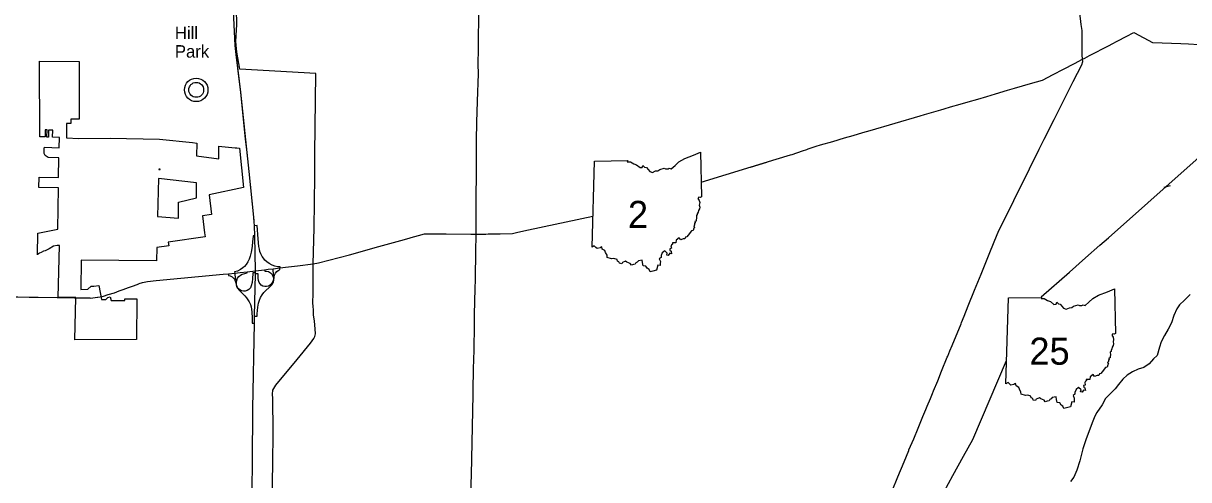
# Model space of a CAD drawing. Extents: x 0 to 750, y 0 to 507.
# Drawn here: x 229.9 to 327.4, y 215 to 253.1 of the extents above; entities that cross this region are included whole.
import ezdxf

# ---------------------------------------------------------------- set-up
doc = ezdxf.new("R2010")
doc.units = 0
for name, color, linetype in [('DV_X_Corp_Line', 7, 'Continuous'), ('GM_P_US_Alignment', 7, 'Continuous'), ('GM_X_Corporation_Text', 7, 'Continuous'), ('GM_X_County', 7, 'Continuous'), ('GM_X_Interchange_Ramps', 7, 'Continuous'), ('GM_X_Interstate_Route', 7, 'Continuous'), ('GM_X_Rail_Line', 7, 'Continuous'), ('GM_X_State_Route', 7, 'Continuous'), ('GM_X_US_Route', 7, 'Continuous')]:
    doc.layers.add(name, color=color, linetype=linetype)

msp = doc.modelspace()

# ---------------------------------------------------------------- linework, layer by layer
at = {"layer": 'DV_X_Corp_Line'}
for points in [[(250.728, 213.571), (250.775, 216.198), (250.812, 218.983), (250.784, 221.74), (250.771, 222.115), (250.783, 222.441), (251.043, 222.865), (252.824, 224.992), (253.938, 226.351), (254.223, 226.765), (254.302, 226.926), (254.355, 227.142), (254.341, 227.553), (254.265, 228.214), (254.201, 228.725), (254.182, 229.151), (254.149, 229.431), (254.127, 229.722), (254.15, 230.504), (254.168, 231.793), (254.166, 232.98), (254.25, 235.984), (254.29, 240.326), (254.295, 242.177), (254.377, 248.889), (248.037, 249.252), (247.783, 250.688), (247.693, 251.561), (247.74, 252.545), (247.768, 252.975), (247.752, 254.307)], [(327.486, 230.432), (327.021, 229.948), (326.609, 229.574), (326.377, 229.222), (326.142, 228.674), (325.925, 228.071), (325.66, 227.538), (325.354, 226.992), (325.079, 226.465), (324.941, 226.02), (324.733, 225.326), (324.447, 225.05), (324.084, 224.636), (323.628, 224.337), (323.164, 224.18), (322.675, 223.963), (322.229, 223.695), (321.877, 223.36), (321.513, 222.9), (321.216, 222.544), (320.752, 222.065), (320.42, 221.73), (320.13, 221.218), (319.943, 220.942), (319.698, 220.579), (319.537, 220.25), (319.301, 219.703), (319.101, 219.184), (318.796, 218.361), (318.52, 217.538), (318.261, 216.544), (318.011, 215.76), (317.77, 215.163), (317.497, 214.791)]]:
    msp.add_lwpolyline(points, dxfattribs=at)
for points in [[(231.101, 233.751), (231.128, 235.547), (232.799, 235.875), (232.858, 239.353), (231.22, 239.38), (231.234, 240.233), (232.873, 240.208), (232.901, 241.86), (231.986, 241.887), (231.757, 242.054), (231.679, 242.205), (231.675, 242.326), (231.675, 242.509), (231.679, 242.592), (231.703, 242.73), (232.924, 242.693), (232.947, 243.557), (232.376, 243.574), (232.382, 244.171), (232.033, 244.174), (232.025, 243.584), (231.9, 243.588), (231.908, 244.175), (231.752, 244.177), (231.743, 243.592), (231.31, 243.604), (231.266, 249.931), (234.598, 249.898), (234.592, 245.075), (233.902, 245.076), (233.901, 244.716), (233.537, 244.716), (233.535, 243.527), (234.578, 243.474), (237.198, 243.497), (241.303, 243.418), (244.056, 243.124), (244.419, 243.076), (244.416, 242.005), (246.261, 241.758), (246.267, 242.832), (246.53, 242.802), (247.641, 242.693), (247.781, 242.676), (247.997, 242.645), (248.343, 239.366), (245.454, 238.751), (245.654, 237.122), (244.899, 237.015), (245.076, 235.574), (245.117, 235.239), (242.047, 234.807), (242.087, 234.485), (241.085, 234.344), (241.06, 233.249), (234.764, 233.302), (234.735, 230.859), (235.319, 230.869), (235.587, 231.138), (235.653, 231.134), (235.748, 231.132), (235.812, 231.138), (236.226, 231.17), (236.457, 230.014), (236.83, 230.021), (236.994, 230.185), (237.188, 230.231), (237.277, 229.942), (238.402, 229.922), (238.402, 230.072), (239.426, 230.067), (239.373, 226.671), (234.238, 226.632), (234.326, 230.167), (232.83, 230.187), (232.947, 234.524), (232.76, 234.527), (232.446, 234.476), (232.093, 234.256), (231.907, 234.173), (231.736, 234.091), (231.606, 234.038), (231.42, 233.945), (231.284, 233.872), (231.113, 233.76)], [(241.243, 240.877), (241.356, 240.866), (241.356, 240.904), (241.244, 240.916)], [(241.145, 236.949), (242.894, 236.796), (242.894, 238.158), (244.41, 238.508), (244.412, 239.759), (241.218, 240.131)]]:
    msp.add_lwpolyline(points, close=True, dxfattribs=at)
for radius in [0.982, 0.623]:
    msp.add_circle((244.38, 247.529), radius, dxfattribs=at)
at = {"layer": 'GM_P_US_Alignment'}
msp.add_lwpolyline([(249.219, 236.614), (248.814, 240.716), (248.102, 247.343), (247.632, 251.233), (247.516, 253.545), (247.395, 263.332), (247.521, 274.256), (248.511, 282.211), (248.511, 282.211), (248.382, 282.254), (248.418, 286.54), (248.262, 289.495), (248.064, 293.827), (247.886, 297.091), (248.325, 298.001), (248.704, 298.832), (249.492, 299.601), (250.125, 299.961), (251.804, 300.69), (255.795, 301.978), (256.69, 302.166), (257.425, 302.18), (263.283, 302.22)], dxfattribs=at)
at = {"layer": 'GM_X_Corporation_Text'}
msp.add_line((277.484, 234.386), (277.685, 241.568), dxfattribs=at)
msp.add_line((277.484, 234.386), (277.685, 241.568), dxfattribs=at)
for points in [[(277.685, 241.568), (280.472, 241.615), (280.428, 241.528), (280.691, 241.509), (280.97, 241.356), (281.206, 241.259), (281.495, 241.031), (281.668, 241.033), (281.741, 241.221), (281.874, 241.076), (282.031, 241.05), (282.302, 240.707), (282.527, 240.632), (282.795, 240.75), (282.996, 240.769), (283.143, 240.886), (283.525, 240.985), (283.632, 240.926), (283.834, 240.938), (283.936, 240.982), (284.112, 240.942), (284.423, 241.204), (284.743, 241.511), (285.235, 241.802), (285.97, 242.077), (286.551, 242.323), (286.636, 238.597)], [(277.685, 241.568), (280.472, 241.615), (280.428, 241.528), (280.691, 241.509), (280.97, 241.356), (281.206, 241.259), (281.495, 241.031), (281.668, 241.033), (281.741, 241.221), (281.874, 241.076), (282.031, 241.05), (282.302, 240.707), (282.527, 240.632), (282.795, 240.75), (282.996, 240.769), (283.143, 240.886), (283.525, 240.985), (283.632, 240.926), (283.834, 240.938), (283.936, 240.982), (284.112, 240.942), (284.423, 241.204), (284.743, 241.511), (285.235, 241.802), (285.97, 242.077), (286.551, 242.323), (286.636, 238.597)], [(286.636, 238.597), (286.55, 238.544), (286.416, 238.569), (286.326, 238.464), (286.437, 238.29), (286.49, 238.106), (286.443, 237.903), (286.489, 237.735), (286.458, 237.595), (286.374, 237.455), (286.345, 237.322), (286.274, 237.182), (286.28, 237.104), (286.212, 237.042), (286.224, 236.809), (286.19, 236.679), (286.202, 236.568), (286.091, 236.539), (286.116, 236.447), (286.046, 236.376), (286.061, 236.253), (285.982, 236.175), (286.059, 236.019), (285.997, 235.969), (285.946, 235.779), (285.804, 235.741), (285.521, 235.393), (285.421, 235.261), (285.308, 235.229), (285.246, 235.094), (285.108, 235.093), (284.899, 235), (284.764, 235.161), (284.526, 234.967), (284.499, 234.743), (284.199, 234.75), (284.211, 234.637), (284.144, 234.604), (284.083, 234.49), (284.119, 234.289), (283.978, 234.237), (283.995, 234.12), (284.085, 234.049), (284.125, 233.825), (283.976, 233.871), (283.854, 233.682), (283.728, 233.726), (283.769, 233.886), (283.557, 234.078), (283.356, 233.924), (283.252, 233.678), (283.25, 233.513), (283.101, 233.413), (283.197, 233.18), (283.179, 233.019), (283.182, 232.866), (282.995, 232.872), (282.882, 232.459)], [(286.636, 238.597), (286.55, 238.544), (286.416, 238.569), (286.326, 238.464), (286.437, 238.29), (286.49, 238.106), (286.443, 237.903), (286.489, 237.735), (286.458, 237.595), (286.374, 237.455), (286.345, 237.322), (286.274, 237.182), (286.28, 237.104), (286.212, 237.042), (286.224, 236.809), (286.19, 236.679), (286.202, 236.568), (286.091, 236.539), (286.116, 236.447), (286.046, 236.376), (286.061, 236.253), (285.982, 236.175), (286.059, 236.019), (285.997, 235.969), (285.946, 235.779), (285.804, 235.741), (285.521, 235.393), (285.421, 235.261), (285.308, 235.229), (285.246, 235.094), (285.108, 235.093), (284.899, 235), (284.764, 235.161), (284.526, 234.967), (284.499, 234.743), (284.199, 234.75), (284.211, 234.637), (284.144, 234.604), (284.083, 234.49), (284.119, 234.289), (283.978, 234.237), (283.995, 234.12), (284.085, 234.049), (284.125, 233.825), (283.976, 233.871), (283.854, 233.682), (283.728, 233.726), (283.769, 233.886), (283.557, 234.078), (283.356, 233.924), (283.252, 233.678), (283.25, 233.513), (283.101, 233.413), (283.197, 233.18), (283.179, 233.019), (283.182, 232.866), (282.995, 232.872), (282.882, 232.459)], [(282.882, 232.459), (282.556, 232.38), (282.331, 232.333), (282.251, 232.52), (282.09, 232.619), (281.985, 232.808), (281.753, 232.833), (281.698, 233.092), (281.672, 233.303), (281.355, 233.251), (281.268, 233.122), (281.156, 233.088), (281.091, 232.958), (280.937, 232.947), (280.773, 232.886), (280.665, 233.013), (280.396, 233.141), (280.275, 233.207), (280.022, 233.104), (279.968, 232.983), (279.766, 233.037), (279.719, 233.172), (279.597, 233.212), (279.57, 233.355), (279.309, 233.431), (279.11, 233.401), (278.758, 233.516), (278.737, 233.704), (278.617, 233.934), (278.554, 234.093), (278.332, 234.214), (278.287, 234.404), (278.216, 234.398), (278.151, 234.321), (277.904, 234.286), (277.805, 234.364), (277.667, 234.496), (277.484, 234.386)], [(282.882, 232.459), (282.556, 232.38), (282.331, 232.333), (282.251, 232.52), (282.09, 232.619), (281.985, 232.808), (281.753, 232.833), (281.698, 233.092), (281.672, 233.303), (281.355, 233.251), (281.268, 233.122), (281.156, 233.088), (281.091, 232.958), (280.937, 232.947), (280.773, 232.886), (280.665, 233.013), (280.396, 233.141), (280.275, 233.207), (280.022, 233.104), (279.968, 232.983), (279.766, 233.037), (279.719, 233.172), (279.597, 233.212), (279.57, 233.355), (279.309, 233.431), (279.11, 233.401), (278.758, 233.516), (278.737, 233.704), (278.617, 233.934), (278.554, 234.093), (278.332, 234.214), (278.287, 234.404), (278.216, 234.398), (278.151, 234.321), (277.904, 234.286), (277.805, 234.364), (277.667, 234.496), (277.484, 234.386)]]:
    msp.add_lwpolyline(points, dxfattribs=at)
at = {"layer": 'GM_X_County'}
msp.add_lwpolyline([(327.486, 230.432), (327.021, 229.948), (326.609, 229.574), (326.377, 229.222), (326.142, 228.674), (325.925, 228.071), (325.66, 227.538), (325.354, 226.992), (325.079, 226.465), (324.941, 226.02), (324.733, 225.326), (324.447, 225.05), (324.084, 224.636), (323.628, 224.337), (323.164, 224.18), (322.675, 223.963), (322.229, 223.695), (321.877, 223.36), (321.513, 222.9), (321.216, 222.544), (320.752, 222.065), (320.42, 221.73), (320.13, 221.218), (319.698, 220.579), (319.537, 220.25), (319.301, 219.703), (319.101, 219.184), (318.796, 218.361), (318.52, 217.538), (318.261, 216.544), (318.011, 215.76), (317.77, 215.163), (317.497, 214.791)], dxfattribs=at)
at = {"layer": 'GM_X_Interchange_Ramps'}
for points in [[(251.403, 232.656), (251.394, 232.728), (251.211, 232.732), (250.943, 232.793), (250.727, 232.879), (250.47, 233.01), (250.285, 233.146), (250.125, 233.297), (249.996, 233.462), (249.893, 233.616), (249.79, 233.816), (249.713, 234.031), (249.661, 234.23), (249.624, 234.449), (249.571, 235.09), (249.477, 236.184), (249.263, 236.167)], [(249.283, 235.322), (249.132, 235.319), (249.132, 235.278), (249.101, 234.867), (249.05, 234.441), (248.963, 233.968), (248.882, 233.633), (248.8, 233.38), (248.704, 233.166), (248.566, 232.948), (248.409, 232.781), (248.271, 232.649), (248.083, 232.512), (247.845, 232.385), (247.595, 232.321), (247.603, 232.222)], [(247.069, 232.162), (247.085, 232.016), (247.225, 231.977), (247.392, 231.894), (247.497, 231.802), (247.583, 231.7), (247.62, 231.612), (247.637, 231.572), (247.681, 231.394), (247.71, 231.231), (247.754, 231.089), (247.829, 230.946), (247.964, 230.792), (248.442, 230.31), (248.593, 230.146), (248.708, 229.977), (248.818, 229.808), (248.907, 229.604), (248.966, 229.406), (249.009, 229.192), (249.032, 228.953), (249.048, 228.476), (249.058, 228.048), (249.247, 228.045)], [(247.603, 232.222), (247.617, 232.095), (247.658, 231.628), (247.62, 231.612)], [(249.326, 232.23), (249.117, 232.234), (249.117, 232.197), (249.082, 231.765), (249.048, 231.426), (248.989, 231.162), (248.906, 230.985), (248.778, 230.85), (248.645, 230.77), (248.477, 230.721), (248.339, 230.717), (248.177, 230.749), (248.021, 230.817), (247.92, 230.914), (247.845, 231.017), (247.785, 231.144), (247.756, 231.292), (247.748, 231.439), (247.77, 231.611), (247.843, 231.788), (247.956, 231.939), (248.074, 232.035), (248.212, 232.12), (248.451, 232.193), (248.65, 232.237), (248.639, 232.337)], [(249.258, 228.62), (249.473, 228.616), (249.489, 228.825), (249.535, 229.362), (249.598, 229.706), (249.674, 229.969), (249.77, 230.18), (249.891, 230.402), (250.047, 230.602), (250.203, 230.776), (250.467, 231.02), (250.695, 231.239), (250.846, 231.465), (250.885, 231.631), (250.906, 231.847), (250.911, 231.9), (250.939, 232.057), (251.008, 232.213), (251.112, 232.338), (251.231, 232.432), (251.349, 232.501), (251.383, 232.506), (251.366, 232.652)], [(250.102, 232.504), (250.115, 232.39), (250.245, 232.39), (250.417, 232.346), (250.597, 232.241), (250.712, 232.117), (250.795, 231.973), (250.833, 231.815), (250.83, 231.678), (250.797, 231.526), (250.713, 231.376), (250.598, 231.231), (250.423, 231.138), (250.265, 231.09), (250.108, 231.093), (249.961, 231.126), (249.815, 231.21), (249.721, 231.314), (249.632, 231.443), (249.579, 231.601), (249.552, 231.789), (249.548, 232.162), (249.325, 232.166)], [(250.906, 231.847), (250.874, 231.85), (250.825, 232.45), (250.809, 232.587)]]:
    msp.add_lwpolyline(points, dxfattribs=at)
at = {"layer": 'GM_X_Interstate_Route'}
msp.add_line((312.096, 222.962), (312.297, 230.144), dxfattribs=at)
msp.add_line((312.096, 222.962), (312.297, 230.144), dxfattribs=at)
for points in [[(248.927, 239.631), (248.814, 240.716), (248.608, 242.559), (248.515, 243.398), (248.102, 247.343), (247.855, 249.311), (247.851, 249.343), (247.718, 250.487), (247.632, 251.233), (247.516, 253.545), (247.526, 254.828), (247.504, 255.943), (247.509, 256.824), (247.498, 257.56), (247.431, 261), (247.395, 263.332), (247.393, 264.053)], [(249.33, 232.414), (249.283, 235.322), (249.263, 236.167), (249.183, 237.17), (248.927, 239.627), (248.927, 239.631)], [(249.111, 220.891), (249.247, 228.045), (249.258, 228.62), (249.325, 232.166), (249.326, 232.23), (249.33, 232.414)], [(312.297, 230.144), (315.083, 230.19), (315.039, 230.103), (315.302, 230.085), (315.582, 229.932), (315.818, 229.835), (316.107, 229.607), (316.28, 229.609), (316.353, 229.796), (316.485, 229.652), (316.642, 229.626), (316.914, 229.282), (317.138, 229.208), (317.407, 229.326), (317.607, 229.345), (317.754, 229.462), (318.136, 229.561), (318.243, 229.502), (318.445, 229.514), (318.547, 229.558), (318.724, 229.518), (319.035, 229.779), (319.355, 230.087), (319.847, 230.378), (320.582, 230.653), (321.163, 230.899), (321.247, 227.172)], [(312.297, 230.144), (315.083, 230.19), (315.039, 230.103), (315.302, 230.085), (315.582, 229.932), (315.818, 229.835), (316.107, 229.607), (316.28, 229.609), (316.353, 229.796), (316.485, 229.652), (316.642, 229.626), (316.914, 229.282), (317.138, 229.208), (317.407, 229.326), (317.607, 229.345), (317.754, 229.462), (318.136, 229.561), (318.243, 229.502), (318.445, 229.514), (318.547, 229.558), (318.724, 229.518), (319.035, 229.779), (319.355, 230.087), (319.847, 230.378), (320.582, 230.653), (321.163, 230.899), (321.247, 227.172)], [(321.247, 227.172), (321.161, 227.12), (321.028, 227.145), (320.938, 227.04), (321.049, 226.866), (321.101, 226.682), (321.055, 226.479), (321.101, 226.311), (321.07, 226.171), (320.986, 226.031), (320.957, 225.898), (320.885, 225.758), (320.891, 225.68), (320.823, 225.618), (320.836, 225.385), (320.801, 225.255), (320.813, 225.144), (320.703, 225.115), (320.728, 225.023), (320.658, 224.952), (320.673, 224.829), (320.593, 224.751), (320.67, 224.595), (320.608, 224.545), (320.557, 224.355), (320.415, 224.317), (320.132, 223.969), (320.032, 223.837), (319.92, 223.805), (319.858, 223.669), (319.72, 223.669), (319.51, 223.575), (319.375, 223.737), (319.138, 223.543), (319.111, 223.319), (318.811, 223.326), (318.823, 223.213), (318.756, 223.18), (318.695, 223.066), (318.73, 222.865), (318.59, 222.813), (318.607, 222.696), (318.697, 222.625), (318.737, 222.401), (318.587, 222.446), (318.465, 222.258), (318.34, 222.302), (318.381, 222.462), (318.169, 222.654), (317.968, 222.5), (317.863, 222.254), (317.862, 222.089), (317.712, 221.989), (317.808, 221.756), (317.791, 221.595), (317.793, 221.442), (317.606, 221.447), (317.493, 221.035)], [(321.247, 227.172), (321.161, 227.12), (321.028, 227.145), (320.938, 227.04), (321.049, 226.866), (321.101, 226.682), (321.055, 226.479), (321.101, 226.311), (321.07, 226.171), (320.986, 226.031), (320.957, 225.898), (320.885, 225.758), (320.891, 225.68), (320.823, 225.618), (320.836, 225.385), (320.801, 225.255), (320.813, 225.144), (320.703, 225.115), (320.728, 225.023), (320.658, 224.952), (320.673, 224.829), (320.593, 224.751), (320.67, 224.595), (320.608, 224.545), (320.557, 224.355), (320.415, 224.317), (320.132, 223.969), (320.032, 223.837), (319.92, 223.805), (319.858, 223.669), (319.72, 223.669), (319.51, 223.575), (319.375, 223.737), (319.138, 223.543), (319.111, 223.319), (318.811, 223.326), (318.823, 223.213), (318.756, 223.18), (318.695, 223.066), (318.73, 222.865), (318.59, 222.813), (318.607, 222.696), (318.697, 222.625), (318.737, 222.401), (318.587, 222.446), (318.465, 222.258), (318.34, 222.302), (318.381, 222.462), (318.169, 222.654), (317.968, 222.5), (317.863, 222.254), (317.862, 222.089), (317.712, 221.989), (317.808, 221.756), (317.791, 221.595), (317.793, 221.442), (317.606, 221.447), (317.493, 221.035)], [(317.493, 221.035), (317.168, 220.956), (316.942, 220.909), (316.863, 221.096), (316.701, 221.195), (316.596, 221.384), (316.364, 221.409), (316.309, 221.668), (316.284, 221.878), (315.967, 221.827), (315.88, 221.698), (315.767, 221.664), (315.702, 221.534), (315.549, 221.523), (315.384, 221.462), (315.277, 221.589), (315.007, 221.717), (314.886, 221.783), (314.633, 221.68), (314.579, 221.559), (314.378, 221.613), (314.33, 221.748), (314.208, 221.788), (314.181, 221.931), (313.921, 222.007), (313.721, 221.977), (313.37, 222.092), (313.348, 222.28), (313.228, 222.51), (313.166, 222.669), (312.943, 222.79), (312.898, 222.98), (312.827, 222.974), (312.762, 222.897), (312.515, 222.862), (312.417, 222.939), (312.278, 223.071), (312.096, 222.962)], [(317.493, 221.035), (317.168, 220.956), (316.942, 220.909), (316.863, 221.096), (316.701, 221.195), (316.596, 221.384), (316.364, 221.409), (316.309, 221.668), (316.284, 221.878), (315.967, 221.827), (315.88, 221.698), (315.767, 221.664), (315.702, 221.534), (315.549, 221.523), (315.384, 221.462), (315.277, 221.589), (315.007, 221.717), (314.886, 221.783), (314.633, 221.68), (314.579, 221.559), (314.378, 221.613), (314.33, 221.748), (314.208, 221.788), (314.181, 221.931), (313.921, 222.007), (313.721, 221.977), (313.37, 222.092), (313.348, 222.28), (313.228, 222.51), (313.166, 222.669), (312.943, 222.79), (312.898, 222.98), (312.827, 222.974), (312.762, 222.897), (312.515, 222.862), (312.417, 222.939), (312.278, 223.071), (312.096, 222.962)], [(249.053, 214.099), (249.053, 214.125), (249.076, 216.406), (249.111, 220.891)]]:
    msp.add_lwpolyline(points, dxfattribs=at)
at = {"layer": 'GM_X_Rail_Line'}
msp.add_lwpolyline([(325.322, 239.396), (325.861, 239.526)], dxfattribs=at)
at = {"layer": 'GM_X_State_Route'}
for points in [[(318.501, 250.086), (318.698, 250.186), (319.095, 250.392), (320.729, 251.244), (320.982, 251.375), (321.402, 251.594), (322.217, 252.019), (322.741, 252.292), (322.788, 252.316), (322.836, 252.291)], [(322.836, 252.291), (324.341, 251.496), (324.353, 251.495), (325.148, 251.46), (325.937, 251.426), (326.725, 251.391), (327.369, 251.363), (328.215, 251.326), (329.484, 251.27), (329.568, 251.266), (329.634, 251.263)], [(307.459, 246.098), (308.277, 246.337), (308.934, 246.528), (309.731, 246.761), (310.497, 246.985), (311.216, 247.195), (312.234, 247.492), (312.823, 247.664), (314.141, 248.049), (315.153, 248.344), (315.163, 248.349), (316.031, 248.8), (316.895, 249.249), (317.823, 249.731), (318.501, 250.086)], [(304.93, 245.36), (305.288, 245.464), (306.051, 245.687), (306.637, 245.858), (306.938, 245.946), (307.459, 246.098)], [(295.457, 242.556), (295.56, 242.591), (296.212, 242.814), (296.591, 242.925), (297.617, 243.224), (298.59, 243.509), (299.321, 243.722), (300.131, 243.958), (300.731, 244.134), (304.93, 245.36)], [(286.608, 239.828), (292.883, 241.728), (294.086, 242.093)], [(294.086, 242.093), (294.211, 242.131)], [(294.211, 242.131), (295.084, 242.429)], [(295.084, 242.429), (295.454, 242.555), (295.457, 242.556)], [(315.027, 230.237), (317.408, 232.295), (318.733, 233.495), (319.956, 234.55), (320.671, 235.154), (323.97, 238.099), (328.743, 242.358)], [(290.744, 241.067), (292.087, 241.487)], [(268.803, 235.487), (268.813, 235.487), (269.786, 235.509), (270.842, 235.533), (271.288, 235.63), (272.169, 235.82), (277.557, 236.987)], [(254.166, 232.98), (254.603, 233.086), (257.206, 233.746), (259.65, 234.435), (261.484, 234.953), (262.182, 235.15)], [(262.182, 235.15), (262.359, 235.2), (262.956, 235.368)], [(262.956, 235.368), (263.457, 235.51), (264.271, 235.501), (265.079, 235.492)], [(265.079, 235.492), (265.167, 235.491), (265.273, 235.49), (267.356, 235.468)], [(267.356, 235.468), (267.37, 235.468), (267.758, 235.464)], [(267.758, 235.464), (268.542, 235.481)], [(268.542, 235.481), (268.593, 235.483), (268.803, 235.487)], [(252.84, 232.825), (254.166, 232.98)], [(239.616, 231.335), (239.884, 231.428), (240.301, 231.512), (241.02, 231.608), (246.647, 232.124)], [(246.647, 232.124), (247.069, 232.162), (247.603, 232.222), (248.047, 232.271)], [(248.047, 232.271), (248.639, 232.337), (249.33, 232.414)], [(249.33, 232.414), (250.102, 232.504), (250.385, 232.537)], [(250.385, 232.537), (250.809, 232.587), (251.366, 232.652), (251.403, 232.656), (251.845, 232.708)], [(251.845, 232.708), (252.84, 232.825)], [(237.943, 230.723), (238.273, 230.844), (238.707, 231.001), (239.124, 231.161), (239.587, 231.325), (239.616, 231.335)], [(229.332, 230.228), (229.451, 230.227), (230.404, 230.216), (231.154, 230.207), (232.743, 230.188)], [(232.743, 230.188), (232.826, 230.187), (233.14, 230.183)], [(233.14, 230.183), (233.802, 230.175)], [(233.802, 230.175), (233.876, 230.174), (234.199, 230.156)], [(234.199, 230.156), (234.332, 230.149), (235.494, 230.138)], [(235.494, 230.138), (235.527, 230.137), (236.137, 230.197)], [(236.137, 230.197), (236.153, 230.198), (236.517, 230.272)], [(236.517, 230.272), (236.616, 230.292), (237.013, 230.416), (237.555, 230.58), (237.943, 230.723)], [(306.929, 213.976), (307.647, 215.3), (308.554, 216.921), (309.333, 218.313), (312.131, 224.907)]]:
    msp.add_lwpolyline(points, dxfattribs=at)
at = {"layer": 'GM_X_US_Route'}
for points in [[(268.064, 261.845), (267.968, 251.349), (267.952, 250.641), (267.949, 250.523), (267.944, 250.115), (267.944, 250.113)], [(318.501, 250.086), (318.468, 250.462), (318.46, 251.007), (318.462, 251.452), (318.465, 252.226), (318.473, 252.492), (318.385, 253.001), (318.2, 254.677), (318.26, 254.96), (318.316, 255.285), (318.396, 256.181), (318.554, 257.401), (318.639, 257.658), (318.833, 257.885), (319.038, 258.024), (319.333, 258.164), (320.089, 258.485), (320.921, 258.739), (321.427, 258.872), (321.684, 258.875), (322.992, 258.836)], [(267.944, 250.113), (267.94, 249.82), (267.937, 249.666), (267.95, 248.878), (267.884, 246.585)], [(316.434, 245.666), (316.512, 245.82), (317.449, 247.675), (317.729, 248.229), (318.434, 249.623), (318.51, 249.891), (318.501, 250.086)], [(267.884, 246.585), (267.883, 246.559), (267.83, 244.831), (267.826, 244.69)], [(311.36, 235.456), (311.434, 235.639), (314.059, 240.935), (314.877, 242.585), (315.214, 243.252), (315.287, 243.396), (316.126, 245.056), (316.23, 245.262), (316.434, 245.666)], [(267.826, 244.69), (267.787, 243.423)], [(267.787, 243.423), (267.779, 243.144), (267.782, 241.623), (267.782, 241.592)], [(267.783, 241.169), (267.783, 241.028), (267.783, 240.226), (267.775, 238.802), (267.769, 237.484), (267.763, 236.41), (267.758, 235.464)], [(267.782, 241.592), (267.783, 241.169)], [(267.758, 235.464), (267.744, 233.966), (267.699, 231.813), (267.696, 231.648)], [(310.015, 232.133), (310.748, 233.943), (311.36, 235.456)], [(308.336, 227.982), (308.386, 228.103), (308.591, 228.609), (308.941, 229.477), (309.468, 230.779), (310.012, 232.125), (310.015, 232.133)], [(267.696, 231.648), (267.681, 230.936), (267.636, 228.771), (267.612, 227.553), (267.555, 224.675), (267.553, 224.543)], [(307.588, 226.158), (307.589, 226.16), (308.336, 227.982)], [(307.19, 225.185), (307.191, 225.188), (307.222, 225.264), (307.409, 225.723), (307.588, 226.158)], [(301.447, 211.327), (301.465, 211.373), (301.84, 212.285), (302.106, 212.923), (302.569, 214.036), (303.051, 215.197), (303.569, 216.442), (303.964, 217.392), (303.986, 217.444), (304.378, 218.382), (304.74, 219.249), (305.151, 220.234), (305.392, 220.81), (305.507, 221.085), (305.775, 221.727), (305.958, 222.165), (306.044, 222.376), (306.389, 223.222), (306.716, 224.023), (307.19, 225.185)], [(267.553, 224.543), (267.504, 222.072), (267.475, 220.716), (267.363, 215.384)], [(267.363, 215.384), (267.326, 213.779)]]:
    msp.add_lwpolyline(points, dxfattribs=at)

# ---------------------------------------------------------------- texts
at = {"layer": 'DV_X_Corp_Line'}
for s, p in [('Hill', (242.599, 251.772)), ('Park', (242.599, 250.222))]:
    msp.add_text(s, height=1.0417, rotation=0.00001, dxfattribs=at).set_placement(p)
at = {"layer": 'GM_X_Corporation_Text'}
msp.add_text('2', height=2.264, dxfattribs=at).set_placement((280.485, 235.988))
at = {"layer": 'GM_X_Interstate_Route'}
msp.add_text('25', height=2.2641, dxfattribs=at).set_placement((314.054, 224.564))

doc.saveas('drawing.dxf')
